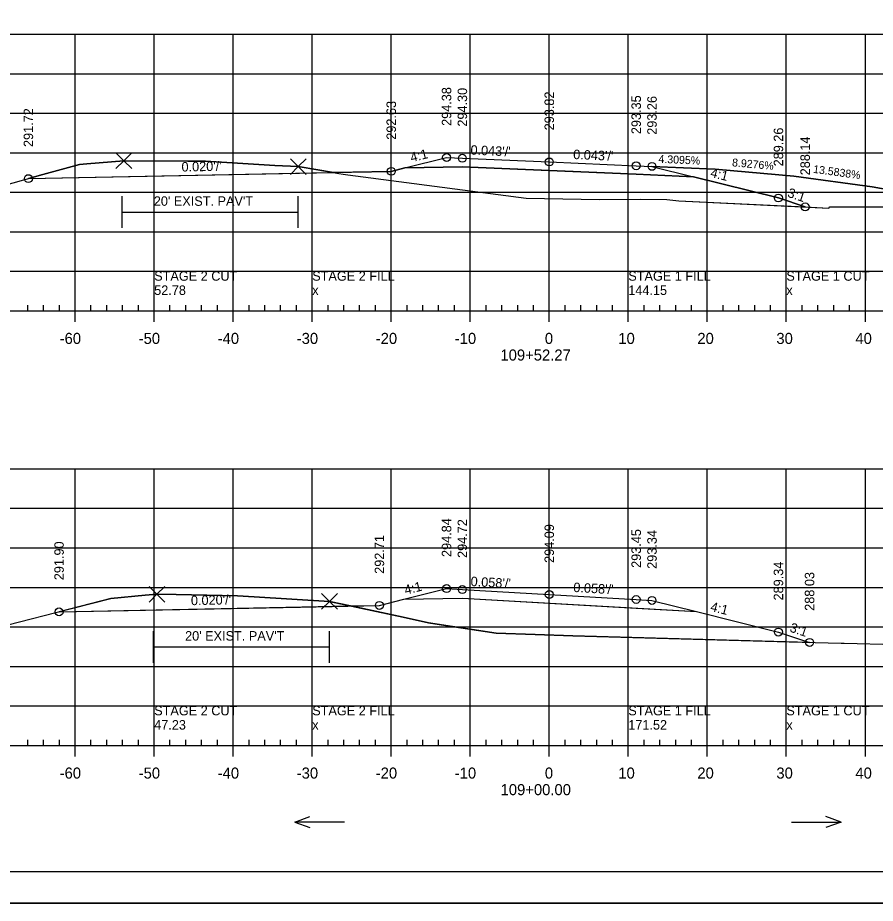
# Model space of a CAD drawing. Extents: x 1370843 to 1371177, y 380307 to 382654.
# Drawn here: x 1370946.4 to 1371055, y 380947.5 to 381059.5 of the extents above; entities that cross this region are included whole.
import ezdxf

# ---------------------------------------------------------------- set-up
doc = ezdxf.new("R2010")
doc.units = 0
for name, color, linetype in [('R_Alt Surface', 7, 'Continuous'), ('R_Axis', 7, 'Continuous'), ('R_Axis Annot', 7, 'Continuous'), ('R_Border', 7, 'Continuous'), ('R_Drive', 7, 'Continuous'), ('R_Exist Surface', 7, 'Continuous'), ('R_Exist Surface Annot', 7, 'Continuous'), ('R_Fin Surface', 7, 'Continuous'), ('R_Fin Surface Annot', 7, 'Continuous'), ('R_Grid', 7, 'Continuous'), ('R_No Plot', 7, 'Continuous'), ('R_Water Annot', 7, 'Continuous')]:
    doc.layers.add(name, color=color, linetype=linetype)

msp = doc.modelspace()

# ---------------------------------------------------------------- linework, layer by layer
at = {"layer": 'R_Alt Surface'}
for points in [[(1370995.45, 381040.53), (1371002.71, 381040.68), (1371013.71, 381040.2), (1371024.71, 381039.73), (1371031.95, 381039.42)], [(1370995.32, 380985.95), (1371002.71, 380986.1), (1371013.71, 380985.47), (1371024.71, 380984.83), (1371032.35, 380984.39)]]:
    msp.add_lwpolyline(points, dxfattribs=at)
at = {"layer": 'R_Axis'}
for p, q in [((1370868.71, 381022.46), (1371158.71, 381022.46)), ((1370947.71, 381022.46), (1370947.71, 381023.16)), ((1370949.71, 381022.46), (1370949.71, 381023.16)), ((1370951.71, 381022.46), (1370951.71, 381023.16)), ((1370953.71, 381021.06), (1370953.71, 381022.46)), ((1370955.71, 381022.46), (1370955.71, 381023.16)), ((1370957.71, 381022.46), (1370957.71, 381023.16)), ((1370959.71, 381022.46), (1370959.71, 381023.16)), ((1370961.71, 381022.46), (1370961.71, 381023.16)), ((1370963.71, 381021.06), (1370963.71, 381022.46)), ((1370965.71, 381022.46), (1370965.71, 381023.16)), ((1370967.71, 381022.46), (1370967.71, 381023.16)), ((1370969.71, 381022.46), (1370969.71, 381023.16)), ((1370971.71, 381022.46), (1370971.71, 381023.16)), ((1370973.71, 381021.06), (1370973.71, 381022.46)), ((1370975.71, 381022.46), (1370975.71, 381023.16)), ((1370977.71, 381022.46), (1370977.71, 381023.16)), ((1370979.71, 381022.46), (1370979.71, 381023.16)), ((1370981.71, 381022.46), (1370981.71, 381023.16)), ((1370983.71, 381021.06), (1370983.71, 381022.46)), ((1370985.71, 381022.46), (1370985.71, 381023.16)), ((1370987.71, 381022.46), (1370987.71, 381023.16)), ((1370989.71, 381022.46), (1370989.71, 381023.16)), ((1370991.71, 381022.46), (1370991.71, 381023.16)), ((1370993.71, 381021.06), (1370993.71, 381022.46)), ((1370995.71, 381022.46), (1370995.71, 381023.16)), ((1370997.71, 381022.46), (1370997.71, 381023.16)), ((1370999.71, 381022.46), (1370999.71, 381023.16)), ((1371001.71, 381022.46), (1371001.71, 381023.16)), ((1371003.71, 381021.06), (1371003.71, 381022.46)), ((1371005.71, 381022.46), (1371005.71, 381023.16)), ((1371007.71, 381022.46), (1371007.71, 381023.16)), ((1371009.71, 381022.46), (1371009.71, 381023.16)), ((1371011.71, 381022.46), (1371011.71, 381023.16)), ((1371013.71, 381021.06), (1371013.71, 381022.46)), ((1371015.71, 381022.46), (1371015.71, 381023.16)), ((1371017.71, 381022.46), (1371017.71, 381023.16)), ((1371019.71, 381022.46), (1371019.71, 381023.16)), ((1371021.71, 381022.46), (1371021.71, 381023.16)), ((1371023.71, 381021.06), (1371023.71, 381022.46)), ((1371025.71, 381022.46), (1371025.71, 381023.16)), ((1371027.71, 381022.46), (1371027.71, 381023.16)), ((1371029.71, 381022.46), (1371029.71, 381023.16)), ((1371031.71, 381022.46), (1371031.71, 381023.16)), ((1371033.71, 381021.06), (1371033.71, 381022.46)), ((1371035.71, 381022.46), (1371035.71, 381023.16)), ((1371037.71, 381022.46), (1371037.71, 381023.16)), ((1371039.71, 381022.46), (1371039.71, 381023.16)), ((1371041.71, 381022.46), (1371041.71, 381023.16)), ((1371043.71, 381021.06), (1371043.71, 381022.46)), ((1371045.71, 381022.46), (1371045.71, 381023.16)), ((1371047.71, 381022.46), (1371047.71, 381023.16)), ((1371049.71, 381022.46), (1371049.71, 381023.16)), ((1371051.71, 381022.46), (1371051.71, 381023.16)), ((1371053.71, 381021.06), (1371053.71, 381022.46)), ((1370868.71, 380967.46), (1371158.71, 380967.46)), ((1370947.71, 380967.46), (1370947.71, 380968.16)), ((1370949.71, 380967.46), (1370949.71, 380968.16)), ((1370951.71, 380967.46), (1370951.71, 380968.16)), ((1370953.71, 380966.06), (1370953.71, 380967.46)), ((1370955.71, 380967.46), (1370955.71, 380968.16)), ((1370957.71, 380967.46), (1370957.71, 380968.16)), ((1370959.71, 380967.46), (1370959.71, 380968.16)), ((1370961.71, 380967.46), (1370961.71, 380968.16)), ((1370963.71, 380966.06), (1370963.71, 380967.46)), ((1370965.71, 380967.46), (1370965.71, 380968.16)), ((1370967.71, 380967.46), (1370967.71, 380968.16)), ((1370969.71, 380967.46), (1370969.71, 380968.16)), ((1370971.71, 380967.46), (1370971.71, 380968.16)), ((1370973.71, 380966.06), (1370973.71, 380967.46)), ((1370975.71, 380967.46), (1370975.71, 380968.16)), ((1370977.71, 380967.46), (1370977.71, 380968.16)), ((1370979.71, 380967.46), (1370979.71, 380968.16)), ((1370981.71, 380967.46), (1370981.71, 380968.16)), ((1370983.71, 380966.06), (1370983.71, 380967.46)), ((1370985.71, 380967.46), (1370985.71, 380968.16)), ((1370987.71, 380967.46), (1370987.71, 380968.16)), ((1370989.71, 380967.46), (1370989.71, 380968.16)), ((1370991.71, 380967.46), (1370991.71, 380968.16)), ((1370993.71, 380966.06), (1370993.71, 380967.46)), ((1370995.71, 380967.46), (1370995.71, 380968.16)), ((1370997.71, 380967.46), (1370997.71, 380968.16)), ((1370999.71, 380967.46), (1370999.71, 380968.16)), ((1371001.71, 380967.46), (1371001.71, 380968.16)), ((1371003.71, 380966.06), (1371003.71, 380967.46)), ((1371005.71, 380967.46), (1371005.71, 380968.16)), ((1371007.71, 380967.46), (1371007.71, 380968.16)), ((1371009.71, 380967.46), (1371009.71, 380968.16)), ((1371011.71, 380967.46), (1371011.71, 380968.16)), ((1371013.71, 380966.06), (1371013.71, 380967.46)), ((1371015.71, 380967.46), (1371015.71, 380968.16)), ((1371017.71, 380967.46), (1371017.71, 380968.16)), ((1371019.71, 380967.46), (1371019.71, 380968.16)), ((1371021.71, 380967.46), (1371021.71, 380968.16)), ((1371023.71, 380966.06), (1371023.71, 380967.46)), ((1371025.71, 380967.46), (1371025.71, 380968.16)), ((1371027.71, 380967.46), (1371027.71, 380968.16)), ((1371029.71, 380967.46), (1371029.71, 380968.16)), ((1371031.71, 380967.46), (1371031.71, 380968.16)), ((1371033.71, 380966.06), (1371033.71, 380967.46)), ((1371035.71, 380967.46), (1371035.71, 380968.16)), ((1371037.71, 380967.46), (1371037.71, 380968.16)), ((1371039.71, 380967.46), (1371039.71, 380968.16)), ((1371041.71, 380967.46), (1371041.71, 380968.16)), ((1371043.71, 380966.06), (1371043.71, 380967.46)), ((1371045.71, 380967.46), (1371045.71, 380968.16)), ((1371047.71, 380967.46), (1371047.71, 380968.16)), ((1371049.71, 380967.46), (1371049.71, 380968.16)), ((1371051.71, 380967.46), (1371051.71, 380968.16)), ((1371053.71, 380966.06), (1371053.71, 380967.46))]:
    msp.add_line(p, q, dxfattribs=at)
at = {"layer": 'R_Border'}
msp.add_line((1371171.89, 380951.46), (1370855.71, 380951.46), dxfattribs=at)
at = {"layer": 'R_Drive'}
msp.add_lwpolyline([(1371024.71, 381040.81), (1371034.7, 381040.38), (1371044.66, 381039.49), (1371054.57, 381038.15), (1371064.41, 381036.35), (1371067.5, 381035.63)], dxfattribs=at)
at = {"layer": 'R_Exist Surface'}
for p, q in [((1371049.21, 381035.63), (1371158.71, 381035.46)), ((1371051.01, 380980.38), (1371158.71, 380977.96))]:
    msp.add_line(p, q, dxfattribs=at)
for points in [[(1370898.84, 381033.74), (1370924.65, 381035.72), (1370937.25, 381036.26), (1370949.62, 381039.69), (1370954.26, 381040.98), (1370955.17, 381041.05), (1370959.87, 381041.45), (1370967.98, 381041.39), (1370970.2, 381041.38), (1370978.97, 381040.86), (1370981.95, 381040.7), (1370984.43, 381040.29), (1370987.06, 381039.84), (1370987.61, 381039.75), (1370988.21, 381039.66), (1370995.66, 381038.67), (1371010.79, 381036.71), (1371020.06, 381036.55), (1371025.27, 381036.6), (1371028.59, 381036.52), (1371030.1, 381036.39), (1371049.09, 381035.45), (1371049.21, 381035.63)], [(1370896.25, 380981.62), (1370917.23, 380981.92), (1370942.02, 380981.92), (1370951.27, 380984.26), (1370958.22, 380986.06), (1370962.56, 380986.45), (1370964.06, 380986.58), (1370966.48, 380986.55), (1370974.26, 380986.38), (1370976.35, 380986.26), (1370985.9, 380985.68), (1370995.2, 380983.67), (1370998.43, 380982.96), (1371001.12, 380982.55), (1371006.98, 380981.67), (1371011.91, 380981.51), (1371016.69, 380981.31), (1371044.06, 380980.55), (1371050.64, 380980.39), (1371051.01, 380980.38)]]:
    msp.add_lwpolyline(points, dxfattribs=at)
at = {"layer": 'R_Exist Surface Annot'}
for p, q in [((1370959.66, 381032.94), (1370959.66, 381036.94)), ((1370981.95, 381032.94), (1370981.95, 381036.94)), ((1370959.66, 381034.94), (1370981.95, 381034.94)), ((1370963.61, 380977.92), (1370963.61, 380981.92)), ((1370985.9, 380977.92), (1370985.9, 380981.92)), ((1370963.61, 380979.92), (1370985.9, 380979.92))]:
    msp.add_line(p, q, dxfattribs=at)
at = {"layer": 'R_Fin Surface'}
for points in [[(1370947.79, 381039.18), (1370983.71, 381039.9), (1370993.71, 381040.1), (1370995.45, 381040.53), (1371000.71, 381041.85), (1371002.71, 381041.76), (1371013.71, 381041.29), (1371024.71, 381040.81), (1371026.71, 381040.73), (1371031.95, 381039.42), (1371042.71, 381036.73), (1371046.09, 381035.6)], [(1370951.67, 380984.36), (1370982.21, 380984.97), (1370992.21, 380985.17), (1370995.32, 380985.95), (1371000.71, 380987.3), (1371002.71, 380987.18), (1371013.71, 380986.55), (1371024.71, 380985.92), (1371026.71, 380985.8), (1371032.35, 380984.39), (1371042.71, 380981.8), (1371046.65, 380980.49)]]:
    msp.add_lwpolyline(points, dxfattribs=at)
at = {"layer": 'R_Grid'}
for p, q in [((1370868.71, 381057.46), (1371158.71, 381057.46)), ((1370953.71, 381022.46), (1370953.71, 381057.46)), ((1370963.71, 381022.46), (1370963.71, 381057.46)), ((1370973.71, 381022.46), (1370973.71, 381057.46)), ((1370983.71, 381022.46), (1370983.71, 381057.46)), ((1370993.71, 381022.46), (1370993.71, 381057.46)), ((1371003.71, 381022.46), (1371003.71, 381057.46)), ((1371013.71, 381022.46), (1371013.71, 381057.46)), ((1371023.71, 381022.46), (1371023.71, 381057.46)), ((1371033.71, 381022.46), (1371033.71, 381057.46)), ((1371043.71, 381022.46), (1371043.71, 381057.46)), ((1371053.71, 381022.46), (1371053.71, 381057.46)), ((1370868.71, 381052.46), (1371158.71, 381052.46)), ((1370868.71, 381047.46), (1371158.71, 381047.46)), ((1370868.71, 381042.46), (1371158.71, 381042.46)), ((1370868.71, 381037.46), (1371158.71, 381037.46)), ((1370868.71, 381032.46), (1371158.71, 381032.46)), ((1370868.71, 381027.46), (1371158.71, 381027.46)), ((1370868.71, 381022.46), (1371158.71, 381022.46)), ((1370868.71, 381002.46), (1371158.71, 381002.46)), ((1370953.71, 380967.46), (1370953.71, 381002.46)), ((1370963.71, 380967.46), (1370963.71, 381002.46)), ((1370973.71, 380967.46), (1370973.71, 381002.46)), ((1370983.71, 380967.46), (1370983.71, 381002.46)), ((1370993.71, 380967.46), (1370993.71, 381002.46)), ((1371003.71, 380967.46), (1371003.71, 381002.46)), ((1371013.71, 380967.46), (1371013.71, 381002.46)), ((1371023.71, 380967.46), (1371023.71, 381002.46)), ((1371033.71, 380967.46), (1371033.71, 381002.46)), ((1371043.71, 380967.46), (1371043.71, 381002.46)), ((1371053.71, 380967.46), (1371053.71, 381002.46)), ((1370868.71, 380997.46), (1371158.71, 380997.46)), ((1370868.71, 380992.46), (1371158.71, 380992.46)), ((1370868.71, 380987.46), (1371158.71, 380987.46)), ((1370868.71, 380982.46), (1371158.71, 380982.46)), ((1370868.71, 380977.46), (1371158.71, 380977.46)), ((1370868.71, 380972.46), (1371158.71, 380972.46)), ((1370868.71, 380967.46), (1371158.71, 380967.46))]:
    msp.add_line(p, q, dxfattribs=at)
at = {"layer": 'R_No Plot'}
msp.add_line((1370843.31, 380947.48), (1371176.64, 380947.48), dxfattribs=at)
for points in [[(1370843.3, 381160.82), (1371176.64, 381160.82), (1371176.64, 380947.48), (1370843.3, 380947.48)], [(1371089.63, 381156.92), (1371089.63, 381147.04), (1371125.36, 381147.04), (1371125.36, 381144.12), (1371148.56, 381144.12), (1371148.56, 381119.79), (1371171.89, 381119.79), (1371171.89, 380951.46), (1370855.71, 380951.46), (1370855.71, 381156.92)], [(1370947.79, 381039.18), (1370986.41, 381039.95), (1370984.43, 381040.29), (1370981.95, 381040.7), (1370978.97, 381040.86), (1370970.2, 381041.38), (1370967.98, 381041.39), (1370959.87, 381041.45), (1370955.17, 381041.05), (1370954.26, 381040.98), (1370949.62, 381039.69)], [(1370986.41, 381039.95), (1370987.06, 381039.84), (1370987.61, 381039.75), (1370988.21, 381039.66), (1370995.66, 381038.67), (1371010.79, 381036.71), (1371020.06, 381036.55), (1371025.27, 381036.6), (1371028.59, 381036.52), (1371030.1, 381036.39), (1371046.09, 381035.6), (1371042.71, 381036.73), (1371031.95, 381039.42), (1371024.71, 381039.73), (1371002.71, 381040.68), (1370995.45, 381040.53), (1370993.71, 381040.1)], [(1371026.71, 381040.73), (1371031.95, 381039.42), (1371042.71, 381036.73), (1371046.09, 381035.6), (1371049.09, 381035.45), (1371049.21, 381035.63), (1371067.5, 381035.63), (1371064.41, 381036.35), (1371054.57, 381038.15), (1371044.66, 381039.49), (1371034.7, 381040.38)], [(1370951.67, 380984.36), (1370988.57, 380985.1), (1370985.9, 380985.68), (1370976.35, 380986.26), (1370974.26, 380986.38), (1370966.48, 380986.55), (1370964.06, 380986.58), (1370962.56, 380986.45), (1370958.22, 380986.06)], [(1370988.57, 380985.1), (1370992.21, 380985.17), (1370995.32, 380985.95), (1371002.71, 380986.1), (1371032.35, 380984.39), (1371042.71, 380981.8), (1371046.65, 380980.49), (1371016.69, 380981.31), (1371011.91, 380981.51), (1371006.98, 380981.67), (1370998.43, 380982.96), (1370995.2, 380983.67)]]:
    msp.add_lwpolyline(points, close=True, dxfattribs=at)
for points in [[(1370959.87, 381041.45), (1370958.87, 381042.45), (1370959.87, 381041.45), (1370958.87, 381040.45), (1370959.87, 381041.45), (1370960.87, 381040.45), (1370959.87, 381041.45), (1370960.87, 381042.45)], [(1370981.95, 381040.7), (1370980.95, 381041.7), (1370981.95, 381040.7), (1370980.95, 381039.7), (1370981.95, 381040.7), (1370982.95, 381039.7), (1370981.95, 381040.7), (1370982.95, 381041.7)], [(1370964.06, 380986.58), (1370963.06, 380987.58), (1370964.06, 380986.58), (1370963.06, 380985.58), (1370964.06, 380986.58), (1370965.06, 380985.58), (1370964.06, 380986.58), (1370965.06, 380987.58)], [(1370985.9, 380985.68), (1370984.9, 380986.68), (1370985.9, 380985.68), (1370984.9, 380984.68), (1370985.9, 380985.68), (1370986.9, 380984.68), (1370985.9, 380985.68), (1370986.9, 380986.68)]]:
    msp.add_lwpolyline(points, dxfattribs=at)
for centre in [(1371000.71, 381041.85), (1371002.71, 381041.76), (1371013.71, 381041.29), (1370993.71, 381040.1), (1371024.71, 381040.81), (1371026.71, 381040.73), (1370947.79, 381039.18), (1371042.71, 381036.73), (1371046.09, 381035.6), (1371000.71, 380987.3), (1371002.71, 380987.18), (1371013.71, 380986.55), (1370992.21, 380985.17), (1371024.71, 380985.92), (1371026.71, 380985.8), (1370951.67, 380984.36), (1371042.71, 380981.8), (1371046.65, 380980.49)]:
    msp.add_circle(centre, 0.5, dxfattribs=at)
at = {"layer": 'R_Water Annot'}
for p, q in [((1370981.5, 380957.76), (1370983.42, 380958.46)), ((1370987.78, 380957.76), (1370981.5, 380957.76)), ((1370981.5, 380957.76), (1370983.42, 380957.06)), ((1371044.35, 380957.76), (1371050.63, 380957.76)), ((1371050.63, 380957.76), (1371048.71, 380958.46)), ((1371050.63, 380957.76), (1371048.71, 380957.06))]:
    msp.add_line(p, q, dxfattribs=at)

# ---------------------------------------------------------------- texts
at = {"layer": 'R_Axis Annot'}
for s, p in [('-60', (1370951.75, 381018.26)), ('-50', (1370961.75, 381018.26)), ('-40', (1370971.75, 381018.26)), ('-30', (1370981.75, 381018.26)), ('-20', (1370991.75, 381018.26)), ('-10', (1371001.75, 381018.26)), ('0', (1371013.15, 381018.26)), ('10', (1371022.45, 381018.26)), ('20', (1371032.45, 381018.26)), ('30', (1371042.45, 381018.26)), ('40', (1371052.45, 381018.26)), ('109+52.27', (1371007.53, 381016.16)), ('-60', (1370951.75, 380963.26)), ('-50', (1370961.75, 380963.26)), ('-40', (1370971.75, 380963.26)), ('-30', (1370981.75, 380963.26)), ('-20', (1370991.75, 380963.26)), ('-10', (1371001.75, 380963.26)), ('0', (1371013.15, 380963.26)), ('10', (1371022.45, 380963.26)), ('20', (1371032.45, 380963.26)), ('30', (1371042.45, 380963.26)), ('40', (1371052.45, 380963.26)), ('109+00.00', (1371007.55, 380961.16))]:
    msp.add_text(s, height=1.4, dxfattribs=at).set_placement(p)
at = {"layer": 'R_Drive'}
for s, rotation, p in [('4.3095%', 357.5324, (1371027.51, 381041.18)), ('8.9276%', 354.8984, (1371036.81, 381040.75)), ('13.5838%', 352.2644, (1371047.06, 381039.92))]:
    msp.add_text(s, height=1, rotation=rotation, dxfattribs=at).set_placement(p)
at = {"layer": 'R_Exist Surface Annot'}
for p in [(1370963.66, 381035.74), (1370967.62, 380980.72)]:
    msp.add_text("20' EXIST. PAV'T", height=1.2, dxfattribs=at).set_placement(p)
at = {"layer": 'R_Fin Surface Annot'}
for s, rotation, p in [('294.38', 90, (1371001.31, 381045.85)), ('294.30', 90, (1371003.31, 381045.76)), ('293.82', 90, (1371014.31, 381045.29)), ('293.35', 90, (1371025.31, 381044.81)), ('293.26', 90, (1371027.31, 381044.73)), ('292.63', 90, (1370994.31, 381044.1)), ('291.72', 90, (1370948.39, 381043.18)), ('289.26', 90, (1371043.31, 381040.73)), ('288.14', 90, (1371046.69, 381039.6)), ('4:1', 14.0362, (1370996.28, 381041.25)), ("0.043'/'", 357.5324, (1371003.72, 381042.22)), ("0.043'/'", 357.5324, (1371016.72, 381041.66)), ("0.020'/'", 1.1458, (1370967.18, 381040.07)), ('4:1', 345.9638, (1371034.02, 381039.41)), ('3:1', 341.5651, (1371043.77, 381036.9)), ('294.84', 90, (1371001.31, 380991.3)), ('294.72', 90, (1371003.31, 380991.18)), ('294.09', 90, (1371014.31, 380990.55)), ('293.45', 90, (1371025.31, 380989.92)), ('293.34', 90, (1371027.31, 380989.8)), ('291.90', 90, (1370952.27, 380988.36)), ('292.71', 90, (1370992.81, 380989.17)), ('289.34', 90, (1371043.31, 380985.8)), ("0.058'/'", 356.706, (1371003.73, 380987.63)), ('288.03', 90, (1371047.25, 380984.49)), ('4:1', 14.0362, (1370995.53, 380986.52)), ("0.058'/'", 356.706, (1371016.73, 380986.88)), ("0.020'/'", 1.1458, (1370968.37, 380985.2)), ('4:1', 345.9638, (1371034.02, 380984.49)), ('3:1', 341.5651, (1371044.05, 380981.88))]:
    msp.add_text(s, height=1.2, rotation=rotation, dxfattribs=at).set_placement(p)
at = {"layer": 'R_No Plot'}
for s, p in [('STAGE 2 CUT', (1370963.71, 381026.26)), ('STAGE 2 FILL', (1370983.71, 381026.26)), ('STAGE 1 FILL', (1371023.71, 381026.26)), ('STAGE 1 CUT', (1371043.71, 381026.26)), ('52.78', (1370963.71, 381024.46)), ('x', (1370983.71, 381024.46)), ('144.15', (1371023.71, 381024.46)), ('x', (1371043.71, 381024.46)), ('STAGE 2 CUT', (1370963.71, 380971.26)), ('STAGE 2 FILL', (1370983.71, 380971.26)), ('STAGE 1 FILL', (1371023.71, 380971.26)), ('STAGE 1 CUT', (1371043.71, 380971.26)), ('47.23', (1370963.71, 380969.46)), ('x', (1370983.71, 380969.46)), ('171.52', (1371023.71, 380969.46)), ('x', (1371043.71, 380969.46))]:
    msp.add_text(s, height=1.2, dxfattribs=at).set_placement(p)

doc.saveas('drawing.dxf')
